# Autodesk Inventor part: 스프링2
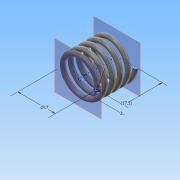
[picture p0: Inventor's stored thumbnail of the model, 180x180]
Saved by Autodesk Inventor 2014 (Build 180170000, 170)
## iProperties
Created: 2016-01
Part Number: 스프링2
Material: 강철, 탄소
Document SubType Name: Modeling
Designer: Administrator
Density: 7.87 g/cm^3
Appearance: 반연마
Mass: 6.44159 g
Surface Area: 16.7002 cm^2
Volume: 0.818499 cm^3
Author: Administrator
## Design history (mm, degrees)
sketch "스케치1"
  geometry: L1 (0, 0)-(8.5, 0); L2 (8.5, 0)-(8.5, 17.5); L3 (8.5, 17.5)-(0, 17.5); L4 (0, 17.5)-(0, 0); C1 r 1 at (8.5, 0)
  constraints: 8 end point, 2 parallel, 1 centre point, 1 coincident, 1 horizontal, 1 perpendicular
  dimensions: "d0" = 17.5 distance of L1.end L2.end (derived); "d1" = 17 diameter of L2 L4; "d2" = 2 diameter of C1
feature "코일1" pitch "d3" = 10; turns "d5" = 5; dims "d4" = 17.5 (= d0), "d6" = 0, angle "d7" = 90 deg, angle "d8" = 90 deg, "d9" = 0, "d10" = 0
node "작업 평면1"
sketch "스케치2"
  geometry: L1 (-7.5, 0)-(-9.5, 0) reference; L2 (-7.5, 0)-(-9.5, 0) reference; 1 further point
  constraints: 2 horizontal alignment
extrude "돌출1" cut sketch "스케치2" distance "d12" = 10; taper "d13" = 0 deg
node "작업 평면2"
sketch "스케치3"
  geometry: L1 (-9.5, 0)-(-7.5, 0) reference; 1 further point
  constraints: 1 horizontal alignment
extrude "돌출2" cut sketch "스케치3" distance "d15" = 10; taper "d16" = 0 deg
node "솔리드1"
node "절단 모서리 투영1"
node "절단 모서리 투영2"
node "절단 모서리 투영3"
other parameters: "d11" = 0, "d14" = 17.5 (= d0)
